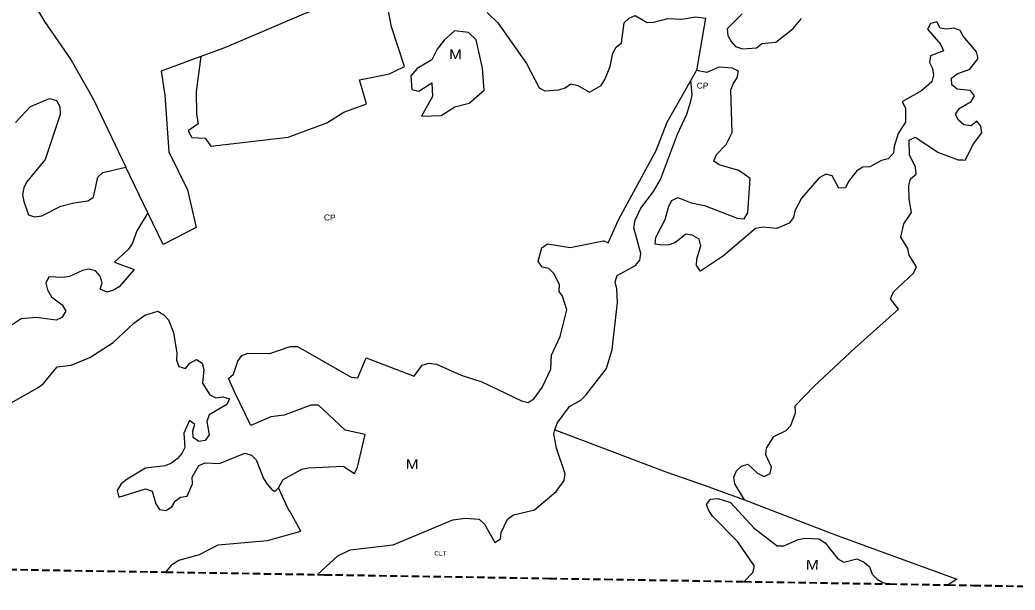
# Model space of a CAD drawing. Extents: x 713589 to 726391, y 7177764 to 7191819.
# Drawn here: x 719111 to 720180, y 7177859 to 7178472 of the extents above; entities that cross this region are included whole.
import ezdxf
from ezdxf.enums import TextEntityAlignment as Align

# ---------------------------------------------------------------- set-up
doc = ezdxf.new("R2010")
doc.units = 0
doc.header["$LTSCALE"] = 2.6
doc.linetypes.add('MEDIUM_DASHED', pattern=[4.5, 3, -1.5])
doc.layers.add('63', color=7, linetype='Continuous', lineweight=25)

msp = doc.modelspace()

# ---------------------------------------------------------------- linework, layer by layer
at = {"layer": '63'}
for p, q in [((719831.78, 7178406.88), (719837.95, 7178417.68)), ((719248.07, 7178264.59), (719224.52, 7178313.68))]:
    msp.add_line(p, q, dxfattribs=at)
at = {"layer": '63', "linetype": 'MEDIUM_DASHED', "lineweight": 40}
msp.add_line((719267.44, 7177878.58), (719430.3, 7177875.9), dxfattribs=at)
at = {"layer": '63'}
for points in [[(718838.82, 7179163.06), (718828.12, 7179158.53), (718794.44, 7179144.27), (718739.17, 7179106.93), (718770.73, 7179057.83), (718801.73, 7179009.6), (718825.05, 7178971.22), (718875.74, 7178887.82), (718880.38, 7178880.19), (718880.89, 7178879.35), (718890.45, 7178864.16), (718971.65, 7178735.2), (719013.14, 7178669.3), (719106.43, 7178521.14), (719111.47, 7178513.14), (719136.8, 7178470.37), (719165.62, 7178428.86), (719189.56, 7178386.56), (719224.52, 7178313.68)], [(719440.31, 7178709.52), (719462.37, 7178680.83), (719480.8, 7178653.18), (719477.83, 7178644.3), (719470.92, 7178641.99), (719455.13, 7178659.44), (719439.66, 7178653.85), (719439.33, 7178637.39), (719450.19, 7178627.52), (719433.73, 7178614.69), (719448.21, 7178610.74), (719461.05, 7178610.73), (719460.06, 7178596.58), (719440.08, 7178581.73), (719488.64, 7178506.58), (719415.46, 7178478.26), (719343.97, 7178447.76), (719330.5, 7178442.01), (719305.1, 7178432.59)], [(719305.1, 7178432.59), (719300.09, 7178395.22), (719300.42, 7178370.54), (719302.06, 7178360.34), (719291.53, 7178352.77), (719295.15, 7178345.53), (719309.63, 7178344.87), (719315.88, 7178336.31), (719398.8, 7178345.84), (719440.6, 7178361.3), (719458.7, 7178372.82), (719483.05, 7178381.7), (719475.49, 7178407.69), (719507.76, 7178413.92), (719513.53, 7178416.75), (719523.87, 7178421.84), (719510.05, 7178464.62), (719501.14, 7178511.41), (719506.24, 7178513.39), (719529.42, 7178523.4)], [(719612.72, 7178479.77), (719624.24, 7178468.88), (719655.16, 7178425.1), (719668.65, 7178399.1), (719674.9, 7178395.81), (719689.71, 7178396.8), (719696.62, 7178399.1), (719702.88, 7178403.38), (719710.12, 7178401.4), (719722.62, 7178394.49), (719735.45, 7178401.4)], [(719735.45, 7178401.4), (719739.4, 7178407.98), (719745, 7178421.8), (719747.96, 7178436.28), (719751.59, 7178442.53), (719757.18, 7178447.46), (719760.15, 7178468.85), (719765.41, 7178473.79), (719771.99, 7178476.75), (719784.83, 7178469.18), (719792.07, 7178469.5), (719806.87, 7178473.45), (719822.01, 7178472.79), (719837.15, 7178475.42), (719847.65, 7178473.86), (719837.95, 7178417.68)], [(719887.05, 7178478.53), (719870.84, 7178462.32), (719871.49, 7178455.08), (719875.11, 7178448.82), (719879.72, 7178443.23), (719887.29, 7178440.92), (719902.42, 7178441.91), (719908.02, 7178446.52), (719923.16, 7178448.16), (719941.59, 7178462.63), (719950.8, 7178473.49)], [(719889.25, 7177956.08), (719878.98, 7177973.32), (719877.99, 7177980.56), (719880.95, 7177987.47), (719886.22, 7177992.4), (719893.13, 7177994.37), (719903.33, 7177984.83), (719910.57, 7177981.21), (719917.15, 7177984.5), (719918.47, 7177991.41), (719912.22, 7178004.57), (719913.21, 7178011.81), (719921.11, 7178024.32), (719934.27, 7178030.89), (719939.21, 7178036.16), (719944.15, 7178049.65), (719943.83, 7178057.14), (719964.44, 7178078.29), (720008.17, 7178119.15), (720054.82, 7178161.09), (720046.51, 7178172.38), (720049.47, 7178179.61), (720071.19, 7178199.68), (720074.16, 7178206.59), (720066.26, 7178219.1), (720064.95, 7178226.34), (720057.38, 7178238.52), (720060.67, 7178252.67), (720068.9, 7178265.17), (720066.27, 7178279.32), (720065.95, 7178293.8), (720067.92, 7178301.04), (720073.85, 7178306.3), (720073.19, 7178313.87), (720066.61, 7178327.03), (720066.28, 7178342.83), (720072.87, 7178346.12), (720097.87, 7178329.33), (720119.26, 7178321.76), (720124.2, 7178321.43), (720126.61, 7178321.27), (720135.72, 7178338.87), (720144.6, 7178350.71), (720143.29, 7178357.62), (720139.01, 7178363.22), (720133.09, 7178358.28), (720125.19, 7178359.27), (720119.6, 7178364.21), (720116.31, 7178370.46), (720120.26, 7178376.71), (720133.09, 7178384.28), (720136.71, 7178390.53), (720132.44, 7178396.13), (720117.96, 7178397.45), (720112.36, 7178402.05), (720112.04, 7178409.29), (720117.96, 7178413.9), (720131.78, 7178419.16), (720140.67, 7178430.68), (720138.7, 7178437.59), (720124.55, 7178454.37), (720121.26, 7178460.63), (720114.35, 7178463.26), (720106.78, 7178461.95), (720099.87, 7178463.26), (720096.25, 7178469.85), (720089.34, 7178468.2), (720086.05, 7178461.95), (720100.2, 7178445.82), (720103.16, 7178438.91), (720089.33, 7178433.32), (720088.35, 7178426.08), (720091.64, 7178419.83), (720092.62, 7178412.59), (720090.65, 7178405.35), (720079.79, 7178395.81), (720064.95, 7178387.44), (720059.42, 7178384.32), (720059.38, 7178383.64), (720062.34, 7178376.73), (720062.34, 7178362.25), (720054.44, 7178349.74), (720050.16, 7178335.92), (720049.5, 7178328.68), (720043.9, 7178322.76), (720036.66, 7178320.79), (720024.16, 7178314.21), (720016.59, 7178313.88), (720010.34, 7178309.93), (720001.12, 7178298.42), (719998.16, 7178291.51), (719990.92, 7178291.18), (719983.68, 7178304.34), (719976.77, 7178306.32), (719969.53, 7178302.37)], [(719305.1, 7178432.59), (719272.13, 7178420.36), (719262.4, 7178416.75), (719266.2, 7178390.95), (719270.46, 7178330.07), (719290.53, 7178289.26), (719300.07, 7178248.78), (719264.35, 7178230.64), (719248.07, 7178264.59)], [(719969.53, 7178302.37), (719950.77, 7178280.33), (719943.53, 7178266.84), (719942.21, 7178259.6), (719937.6, 7178253.67), (719924.11, 7178247.75), (719908.97, 7178249.4), (719901.4, 7178247.76), (719866.85, 7178218.48), (719842.16, 7178202.03), (719837.89, 7178207.95), (719838.22, 7178215.19), (719842.5, 7178229.34), (719840.52, 7178236.25), (719833.28, 7178240.53), (719826.37, 7178241.85), (719815.18, 7178232.64), (719808.27, 7178230.33), (719800.7, 7178230.01), (719793.46, 7178230.99), (719794.12, 7178238.23), (719804, 7178257.32), (719807.95, 7178271.8), (719811.24, 7178278.05), (719817.82, 7178281.01), (719831.97, 7178275.41), (719846.45, 7178272.45), (719881.66, 7178258.95), (719888.9, 7178258.29), (719892.85, 7178264.54), (719895.49, 7178301.4), (719883.31, 7178310.28), (719862.26, 7178316.21), (719856.33, 7178320.16), (719859.3, 7178327.4), (719869.83, 7178337.93), (719876.08, 7178351.09), (719874.77, 7178396.5), (719877.41, 7178403.41), (719881.36, 7178409.66), (719883, 7178416.9), (719876.42, 7178420.2), (719861.94, 7178421.18), (719848.78, 7178415.59), (719837.95, 7178417.68)], [(719388.54, 7177969.03), (719393.57, 7177977.97), (719413.53, 7177989.05), (719420.81, 7177990.64), (719457.88, 7177992.21), (719470.23, 7177984.61), (719473.4, 7177991.26), (719481.64, 7178026.42), (719460.1, 7178031.18), (719431.6, 7178058.11), (719423.36, 7178058.11), (719394.53, 7178047.35), (719380.28, 7178045.45), (719358.84, 7178036.16), (719341.38, 7178071.49), (719334.57, 7178086.57), (719340.05, 7178091.39), (719344.81, 7178105.33), (719348.92, 7178111.35), (719355.89, 7178113.88), (719379.34, 7178113.56), (719401.2, 7178120.84), (719408.48, 7178120.84), (719414.82, 7178117.67), (719466.45, 7178087.88), (719473.74, 7178087.25), (719482.69, 7178108.81), (719534.36, 7178089.16), (719542.8, 7178100.86), (719550.08, 7178103.07), (719558.32, 7178102.12), (719584.93, 7178090.08), (719607.1, 7178083.11), (719649.87, 7178062.51), (719656.84, 7178060.92), (719663.49, 7178065.04), (719672.04, 7178076.76), (719681.23, 7178096.71), (719681.87, 7178111.6), (719691.38, 7178131.88), (719698.35, 7178160.39), (719693.6, 7178174.96), (719690.24, 7178180), (719690.56, 7178187.6), (719684.42, 7178199.35), (719679.04, 7178204.74), (719671.75, 7178206.33), (719667.63, 7178212.66), (719671.44, 7178226.92), (719677.77, 7178231.35), (719702.17, 7178227.23), (719738.01, 7178234.46), (719738.28, 7178234.51), (719742.81, 7178232.3), (719754.26, 7178257.84), (719794.31, 7178331.46), (719806.23, 7178362.18), (719831.78, 7178406.88)], [(719685.67, 7178031.61), (719688.19, 7178038.42), (719701.19, 7178056.48), (719713.54, 7178063.45), (719718.93, 7178068.51), (719741.11, 7178097.34), (719747.13, 7178117.61), (719752.84, 7178168.3), (719752.21, 7178182.87), (719750.31, 7178190.47), (719752.53, 7178197.44), (719772.17, 7178208.21), (719776.93, 7178213.91), (719777.88, 7178220.88), (719770.28, 7178248.44), (719771.86, 7178256.68), (719777.89, 7178269.66), (719791.51, 7178287.4), (719799.12, 7178300.39), (719817.5, 7178349.17), (719827.32, 7178370.71), (719831.76, 7178384.65), (719833.03, 7178391.62), (719831.78, 7178406.88)], [(719105.74, 7178361.71), (719121.9, 7178378.82), (719142.49, 7178387.69), (719149.78, 7178385.47), (719153.58, 7178378.81), (719153.89, 7178370.26), (719137.73, 7178321.79), (719117.76, 7178297.72), (719114.6, 7178291.39), (719113.33, 7178284.1), (719114.59, 7178276.81), (719119.66, 7178262.56), (719126.31, 7178260.34), (719133.91, 7178261.29), (719154.51, 7178271.74), (719168.45, 7178275.54), (719183.65, 7178277.44), (719189.67, 7178281.55), (719194.43, 7178303.09), (719199.81, 7178307.84), (719224.52, 7178313.68)], [(719248.07, 7178264.59), (719236.23, 7178245.43), (719231.16, 7178231.18), (719227.04, 7178225.16), (719212.09, 7178211.72), (719233.31, 7178203.65), (719217.22, 7178185.24), (719211.2, 7178181.44), (719204.23, 7178179.54), (719196.63, 7178182.71), (719198.84, 7178189.37), (719196.63, 7178196.65), (719191.88, 7178202.35), (719184.59, 7178203.94), (719177.62, 7178202.67), (719163.68, 7178196.34), (719156.71, 7178195.07), (719141.51, 7178196.03), (719138.34, 7178189.06), (719140.24, 7178181.77), (719144.35, 7178174.49), (719156.07, 7178165.93), (719159.87, 7178158.96), (719155.75, 7178152.31), (719149.42, 7178149.14), (719127.88, 7178152), (719112.04, 7178150.73), (719100, 7178142.81)], [(719098.72, 7178059.18), (719130.08, 7178076.92), (719135.78, 7178081.35), (719150.68, 7178099.09), (719165.57, 7178100.99), (719185.52, 7178109.22), (719210.87, 7178125.37), (719233.05, 7178145.96), (719244.77, 7178154.51), (719258.71, 7178158.94), (719265.05, 7178155.14), (719270.11, 7178149.75), (719275.5, 7178136.13), (719279.29, 7178113.96), (719278.98, 7178106.35), (719281.51, 7178099.38), (719288.48, 7178097.48), (719293.23, 7178103.18), (719300.2, 7178106.98), (719306.54, 7178103.18), (719308.12, 7178096.21), (719306.85, 7178081.64), (719314.77, 7178068.96), (719321.1, 7178065.8), (719328.71, 7178066.74), (719335.99, 7178064.84), (719332.82, 7178058.51), (719314.13, 7178047.42), (719311.28, 7178040.45), (719314.13, 7178026.2), (719309.69, 7178019.86), (719302.72, 7178018.91), (719296.7, 7178023.35), (719296.39, 7178030.64), (719298.61, 7178037.29), (719292.9, 7178041.41), (719286.88, 7178027.79), (719287.83, 7178012.58), (719284.66, 7178005.93), (719279.59, 7178000.23), (719273.57, 7177995.48), (719266.6, 7177992.63), (719245.38, 7177990.1), (719225.73, 7177978.38), (719219.4, 7177973.31), (719214.96, 7177966.34), (719216.86, 7177959.06), (719245.69, 7177967.92), (719252.66, 7177965.39), (719256.46, 7177951.76), (719260.57, 7177945.74), (719267.54, 7177944.79), (719273.88, 7177948.59), (719277.37, 7177954.93), (719283.07, 7177959.04), (719290.36, 7177959.99), (719296.06, 7177973.3), (719295.74, 7177980.58), (719302.72, 7177993.25), (719309.69, 7177995.79), (719325.21, 7177995.15), (719352.45, 7178006.23)], [(719430.3, 7177875.9), (719435.51, 7177880.67), (719452.16, 7177895.91), (719465.47, 7177902.56), (719511.72, 7177907.94), (719575.72, 7177934.54), (719589.65, 7177936.44), (719604.23, 7177935.48), (719609.93, 7177930.1), (719621.01, 7177910.45), (719627.03, 7177914.25), (719627.67, 7177921.22), (719634.64, 7177935.48), (719640.97, 7177939.91), (719651.94, 7177942.65), (719663.78, 7177945.61), (719686.91, 7177965.25), (719695.47, 7177976.97), (719696.74, 7177984.25), (719687.24, 7178011.81), (719684.39, 7178027.02), (719685.6, 7178031.41), (719685.67, 7178031.61)], [(719685.67, 7178031.61), (719692.27, 7178029.1), (719805.03, 7177986.22), (719847.09, 7177971.48), (719869.86, 7177963.5), (719889.25, 7177956.08)], [(719352.45, 7178006.23), (719359.42, 7178004.33), (719364.49, 7177999.26), (719372.41, 7177978.99), (719376.21, 7177972.97), (719380.96, 7177967.58), (719384.47, 7177965.29), (719388.54, 7177969.03)], [(719267.44, 7177878.58), (719274.5, 7177887.13), (719281.47, 7177891.25), (719303.65, 7177897.58), (719323.61, 7177907.72), (719376.51, 7177912.46), (719412.34, 7177922.57), (719400.87, 7177943.31), (719399.01, 7177946.67), (719392.87, 7177959.79), (719388.54, 7177969.03)], [(719889.05, 7177868.36), (719898.51, 7177878.09), (719900.1, 7177885.06), (719882.36, 7177911.04), (719855.12, 7177938.61), (719851.01, 7177944.63), (719848.47, 7177951.28), (719852.91, 7177956.98), (719860.83, 7177957.61), (719874.45, 7177953.17), (719899.79, 7177925.61), (719924.5, 7177906.91), (719931.78, 7177906.91), (719946.99, 7177913.56), (719954.27, 7177914.83), (719969.48, 7177914.19), (719976.13, 7177910.07), (719989.75, 7177892.65), (719996.09, 7177889.16), (720010.03, 7177892.64), (720017.95, 7177889.16), (720023.96, 7177884.09), (720026.81, 7177876.49), (720031.88, 7177870.78), (720038.22, 7177867.3), (720045.25, 7177865.79)], [(719889.25, 7177956.08), (719986.01, 7177919.05), (720117.84, 7177870.81), (720108.51, 7177864.75)]]:
    msp.add_lwpolyline(points, dxfattribs=at)
msp.add_lwpolyline([(719542.28, 7178368.52), (719563.34, 7178369.18), (719578.15, 7178378.39), (719593.29, 7178382.66), (719609.42, 7178396.48), (719607.78, 7178420.18), (719600.87, 7178450.45), (719592.65, 7178458.35), (719577.63, 7178460.28), (719566.65, 7178450.13), (719559.08, 7178440.59), (719553.48, 7178429.07), (719537.69, 7178419.86), (719530.77, 7178411.96), (719531.76, 7178397.15), (719539.33, 7178395.51), (719553.15, 7178404.39), (719554.13, 7178389.58)], close=True, dxfattribs=at)
at = {"layer": '63', "linetype": 'MEDIUM_DASHED', "lineweight": 40}
for points in [[(718923.9, 7177884.23), (719250.63, 7177878.86), (719267.44, 7177878.58)], [(719430.3, 7177875.9), (719438.21, 7177875.77), (719679.96, 7177871.8), (719740.01, 7177870.81), (719889.05, 7177868.36)], [(719889.05, 7177868.36), (720045.25, 7177865.79), (720108.51, 7177864.75)], [(720108.51, 7177864.75), (720135.62, 7177864.3), (720445.89, 7177859.2)]]:
    msp.add_lwpolyline(points, dxfattribs=at)

# ---------------------------------------------------------------- texts
at = {"layer": '63'}
for s, height, width, p in [('M', 10.4, 1.2, (719578.65, 7178429.87)), ('CP', 6.4, 1.05, (719844.29, 7178398.17)), ('CP', 6.4, 1.05, (719443.57, 7178256.43)), ('M', 10.4, 1.2, (719532.05, 7177989.34)), ('CLT', 4.64, 1.15, (719562.54, 7177896.31)), ('M', 10.4, 1.2, (719962.22, 7177881.14))]:
    msp.add_text(s, height=height, rotation=359.062, dxfattribs=dict(at, width=width)).set_placement(p, align=Align.CENTER)

doc.saveas('drawing.dxf')
